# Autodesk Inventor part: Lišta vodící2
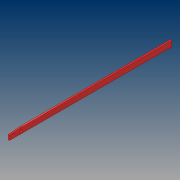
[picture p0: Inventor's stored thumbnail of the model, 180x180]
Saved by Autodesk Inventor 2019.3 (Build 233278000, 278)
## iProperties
Created: 2019-03
Part Number: Lišta vodící2
Material: Ocel, měkká, svařovaná
Document SubType Name: Modeling
Designer: B-hon
Density: 7.85 g/cm^3
Appearance: Světle červená
Author: B-hon
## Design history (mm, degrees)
sketch "Náčrt1"
  geometry: L1 (0, 0)-(5, 0); L2 (5, 0)-(5, 20); L3 (5, 20)-(0, 20); L4 (0, 20)-(0, 0)
  constraints: 8 end point, 2 parallel, 1 horizontal, 1 perpendicular
  dimensions: "d0" = 5 distance of L3.end L2.end; "d1" = 20 distance of L2.end L1.end
extrude "Vysunutí1" new body sketch "Náčrt1" distance "d2" = 555; taper "d3" = 0 deg
chamfer "Zkosení1" distance "d4" = 1.5; stored, may be unused: second distance "d5" = 2, angle "d6" = 85 deg
sketch "Náčrt3"
  geometry: L1 (0, 0)-(-555, 0) reference; 2 further points
  dimensions: "d14" = 8 distance from line of L1 point (-542.855, 8); "d28" = 5 horizontal distance of point (-537.855, 20) point (-542.855, 8)
hole "Díra1" sketch "Náčrt3" at (-542.855, 8) diameter "d15" = 6.5; stored, may be unused: countersink angle "d19" = 90 deg, drill point angle "d21" = 118 deg; dims "d16" = 6, "d17" = 11.4, "d18" = 2, "d20" = 8
node "Upravit přímo1"
pattern_linear "Obdélníkové pole1" dims "d27" = 28
node "Těleso1"
feature "Posunout1" dims "d24" = 28.6
other parameters: "d22" = 0, "d23" = 0
